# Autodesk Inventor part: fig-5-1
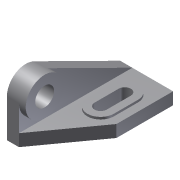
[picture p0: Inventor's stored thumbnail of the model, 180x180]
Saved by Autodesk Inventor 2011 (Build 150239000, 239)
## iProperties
Shininess: 64.0
Length Units: 11272
Angle Units: 11279
Time Units: 11290
Mass Units: 11283
Length Display Precision: 3
Angle Display Precision: 2
Compacted: True
Part Number: fig-5-1
Document SubType Name: Modeling
Created: 2003-01
Designer: Owner
Density: 1 g/cm^3
Density: 0.0
Volumn: 0.0
Area: 0.0
PropertySet Name: Model Information
Control State: 0
Master: False
Checked Out: False
Author: Owner
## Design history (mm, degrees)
sketch "Sketch1"
  geometry: L1 (-795.488, 2648.57)-(-795.488, 3054.97); L2 (1109.512, 1276.97)-(-795.488, 2648.57); L3 (3014.512, 1276.97)-(1109.512, 1276.97); L4 (3014.512, 3054.97)-(3014.512, 1276.97); L5 (-795.488, 3054.97)-(3014.512, 3054.97)
  constraints: 10 end point, 2 horizontal, 2 vertical, 1 other
  dimensions: "d1" = 3810 distance of L1.end L4.start; "d3" = 1778 distance of L4.start L3.start; "d5" = 1905 distance of L3.start L2.start; "d7" = 406.4 distance of L1.start L1.end
extrude "ExtrusionBlind1" new body sketch "Sketch1" distance "d8" = 406.4; taper "d9" = 0 deg
sketch "Sketch2"
  geometry: L1 (916.783, -1839.055)-(3810, -406.4); L2 (0, -406.4)-(0, -1270); L3 (3810, -406.4)-(0, -406.4); L4 (0, -406.4)-(3810, -406.4) reference; L5 (0, 0)-(0, -406.4) reference; A1 r 635 centre (635, -1270) between (0, -1270) and (916.783, -1839.055)
  constraints: 6 end point, 2 collinear, 2 point on circle, 2 tangent, 1 centre point, 1 horizontal, 1 vertical
  dimensions: "d14" = 1270 vertical distance of A1.centre L5.start; "d16" = 635 radius of A1
extrude "ExtrusionBlind2" join sketch "Sketch2" distance "d17" = 406.4; taper "d18" = 0 deg
sketch "Sketch3"
  geometry: C1 r 635 at (635, 1270); A1 r 635 centre (635, 1270) between (916.783, 1839.055) and (0, 1270) reference
  constraints: 1 centre point, 1 concentric
extrude "ExtrusionBlind3" join sketch "Sketch3" distance "d20" = 228.6; taper "d21" = 0 deg
sketch "Sketch4"
  geometry: L1 (1287.312, 1543.67)-(2100.112, 1543.67); L2 (2100.112, 2432.67)-(1287.312, 2432.67); A1 r 444.5 centre (2100.112, 1988.17) between (2100.112, 1543.67) and (2100.112, 2432.67); A2 r 444.5 centre (1287.312, 1988.17) between (1287.312, 2432.67) and (1287.312, 1543.67); 1 further point
  constraints: 4 end point, 4 point on circle, 4 tangent, 2 centre point, 2 horizontal
  dimensions: "d23" = 889 distance of L1.end L2.start; "d25" = 812.8 distance of L2.start L2.end; "d27" = 711.2 vertical distance of A1.centre point (3014.512, 1276.97); "d29" = 914.4 horizontal distance of A1.centre point (3014.512, 1276.97)
extrude "ExtrusionBlind4" join sketch "Sketch4" distance "d30" = 76.2; taper "d31" = 0 deg
sketch "Sketch5"
  geometry: L1 (2100.112, 2191.37)-(1287.312, 2191.37); L2 (1287.312, 1784.97)-(2100.112, 1784.97); A1 r 203.2 centre (1287.312, 1988.17) between (1287.312, 2191.37) and (1287.312, 1784.97); A2 r 203.2 centre (2100.112, 1988.17) between (2100.112, 1784.97) and (2100.112, 2191.37); A3 r 444.5 centre (2100.112, 1988.17) between (2100.112, 1543.67) and (2100.112, 2432.67) reference
  constraints: 4 end point, 4 point on circle, 4 tangent, 2 centre point, 2 horizontal, 1 concentric
  dimensions: "d35" = 812.8 distance of L2.start L2.end; "d37" = 406.4 distance of L2.start L1.end
extrude "ExtrusionThru1" cut sketch "Sketch5" stored distance "d38" = 3.302; taper "d39" = 0 deg
sketch "Sketch6"
  geometry: C1 r 635 at (0, 0) reference; 1 further point
hole "Hole1" sketch "Sketch6" at (0, 0) diameter "d40" = 635; stored, may be unused: countersink angle "d44" = 82 deg, drill point angle "d46" = 118 deg; dims "d41" = 12.7, "d42" = 9.525, "d43" = 6.35, "d45" = 19.05
body "Solid1"
other parameters: "d2" = 1778 (derived), "d4" = 1905 (derived), "d6" = 406.4 (derived), "d10" = 0, "d11" = 0, "d12" = 0 (derived), "d15" = 635 (derived), "d19" = 0, "d22" = 889 (derived), "d24" = 812.8 (derived), "d26" = 711.2 (derived), "d28" = 914.4 (derived), "d32" = 0, "d33" = 0, "d34" = 812.8 (derived), "d36" = 406.4 (derived)
